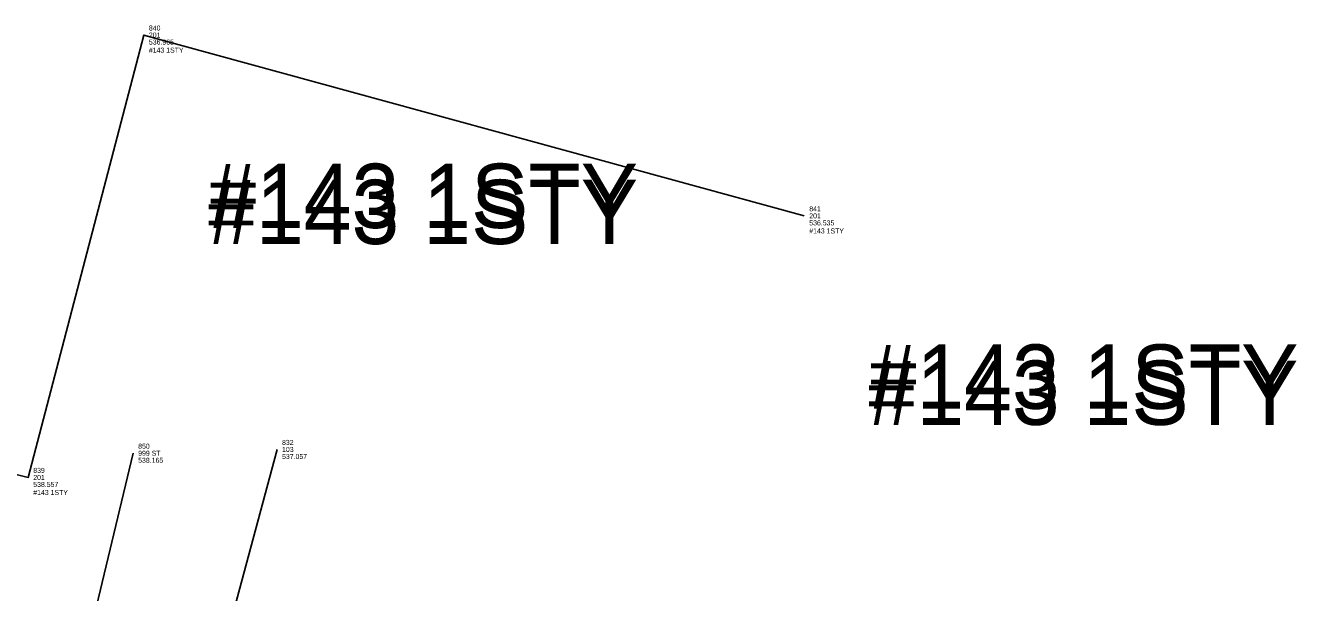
# Model space of a CAD drawing. Extents: x 5447 to 709667, y 4528 to 375505.
# Drawn here: x 706612.3 to 706675.6, y 374943.3 to 374971.5 of the extents above; entities that cross this region are included whole.
import ezdxf

# ---------------------------------------------------------------- set-up
doc = ezdxf.new("R2010")
doc.units = 0
for name, color, linetype in [('SV_BKLN_BKLN', 7, 'Continuous'), ('SV_BLDG_BUILDING', 7, 'Continuous'), ('SV_NODES_ACTIVE_POINT', 7, 'Continuous'), ('SV_NODES_DESCRIPTION', 7, 'Continuous'), ('SV_NODES_ELEVATION', 7, 'Continuous'), ('SV_NODES_PT_NUMBER', 7, 'Continuous'), ('SV_ROAD_DIRTRD', 7, 'Continuous'), ('SV_SURVEY_NOTES', 7, 'Continuous')]:
    doc.layers.add(name, color=color, linetype=linetype)

msp = doc.modelspace()

# ---------------------------------------------------------------- linework, layer by layer
at = {"layer": 'SV_BKLN_BKLN'}
msp.add_lwpolyline([(706617.672, 374950.184), (706610.842, 374921.737), (706609.971, 374912.169), (706636.92, 374904.401), (706652.473, 374902.483), (706662.168, 374904.924)], dxfattribs=at)
at = {"layer": 'SV_BLDG_BUILDING'}
msp.add_lwpolyline([(706575.165, 374958.169), (706612.448, 374948.981), (706618.206, 374970.99), (706651.09, 374961.995)], dxfattribs=at)
at = {"layer": 'SV_NODES_ACTIVE_POINT'}
for p, q in [((706618.206, 374970.99), (706618.206, 374970.99)), ((706651.09, 374961.995), (706651.09, 374961.995)), ((706617.672, 374950.184), (706617.672, 374950.184)), ((706624.837, 374950.373), (706624.837, 374950.373)), ((706612.448, 374948.981), (706612.448, 374948.981))]:
    msp.add_line(p, q, dxfattribs=at)
at = {"layer": 'SV_ROAD_DIRTRD'}
msp.add_lwpolyline([(706664.067, 374910.004), (706652.876, 374908.321), (706634.763, 374914.02), (706616.578, 374920.454), (706620.968, 374935.962), (706624.837, 374950.373)], dxfattribs=at)

# ---------------------------------------------------------------- texts
at = {"layer": 'SV_NODES_DESCRIPTION'}
for s, p in [('201', (706618.456, 374970.865)), ('201', (706651.34, 374961.87)), ('103', (706625.087, 374950.248)), ('999 ST', (706617.922, 374950.059)), ('201', (706612.698, 374948.856))]:
    msp.add_text(s, height=0.25, dxfattribs=at).set_placement(p)
at = {"layer": 'SV_NODES_ELEVATION'}
for s, p in [('536.965', (706618.456, 374970.515)), ('536.535', (706651.34, 374961.52)), ('538.165', (706617.922, 374949.709)), ('537.057', (706625.087, 374949.898)), ('538.557', (706612.698, 374948.506))]:
    msp.add_text(s, height=0.25, dxfattribs=at).set_placement(p)
at = {"layer": 'SV_NODES_PT_NUMBER'}
for s, p in [('840', (706618.456, 374971.215)), ('841', (706651.34, 374962.22)), ('850', (706617.922, 374950.409)), ('832', (706625.087, 374950.598)), ('839', (706612.698, 374949.206))]:
    msp.add_text(s, height=0.25, dxfattribs=at).set_placement(p)
at = {"layer": 'SV_SURVEY_NOTES'}
for height, p in [(0.25, (706618.456, 374970.115)), (3.2, (706621.406, 374961.39)), (3.2, (706621.406, 374961.39)), (3.2, (706621.406, 374961.39)), (3.2, (706621.406, 374961.39)), (3.2, (706621.406, 374961.39)), (3.2, (706621.406, 374961.39)), (3.2, (706621.406, 374961.39)), (3.2, (706621.406, 374961.39)), (3.2, (706621.406, 374960.59)), (3.2, (706621.406, 374960.59)), (3.2, (706621.406, 374960.59)), (0.25, (706651.34, 374961.12)), (3.2, (706654.29, 374952.395)), (3.2, (706654.29, 374952.395)), (3.2, (706654.29, 374952.395)), (3.2, (706654.29, 374952.395)), (3.2, (706654.29, 374952.395)), (3.2, (706654.29, 374952.395)), (3.2, (706654.29, 374952.395)), (3.2, (706654.29, 374952.395)), (3.2, (706654.29, 374951.595)), (3.2, (706654.29, 374951.595)), (3.2, (706654.29, 374951.595)), (0.25, (706612.698, 374948.106))]:
    msp.add_text('#143 1STY', height=height, dxfattribs=at).set_placement(p)

doc.saveas('drawing.dxf')
